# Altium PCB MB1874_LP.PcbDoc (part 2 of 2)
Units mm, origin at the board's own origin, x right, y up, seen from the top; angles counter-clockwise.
Board outline 59.8 x 34.35 mm, 2 copper layers (Top Layer, Bottom Layer), stack 0.78 mm thick; 77 components, 63 nets, 242 pads, 939 vias.
Unrouted connection lines stored in the file: 1.
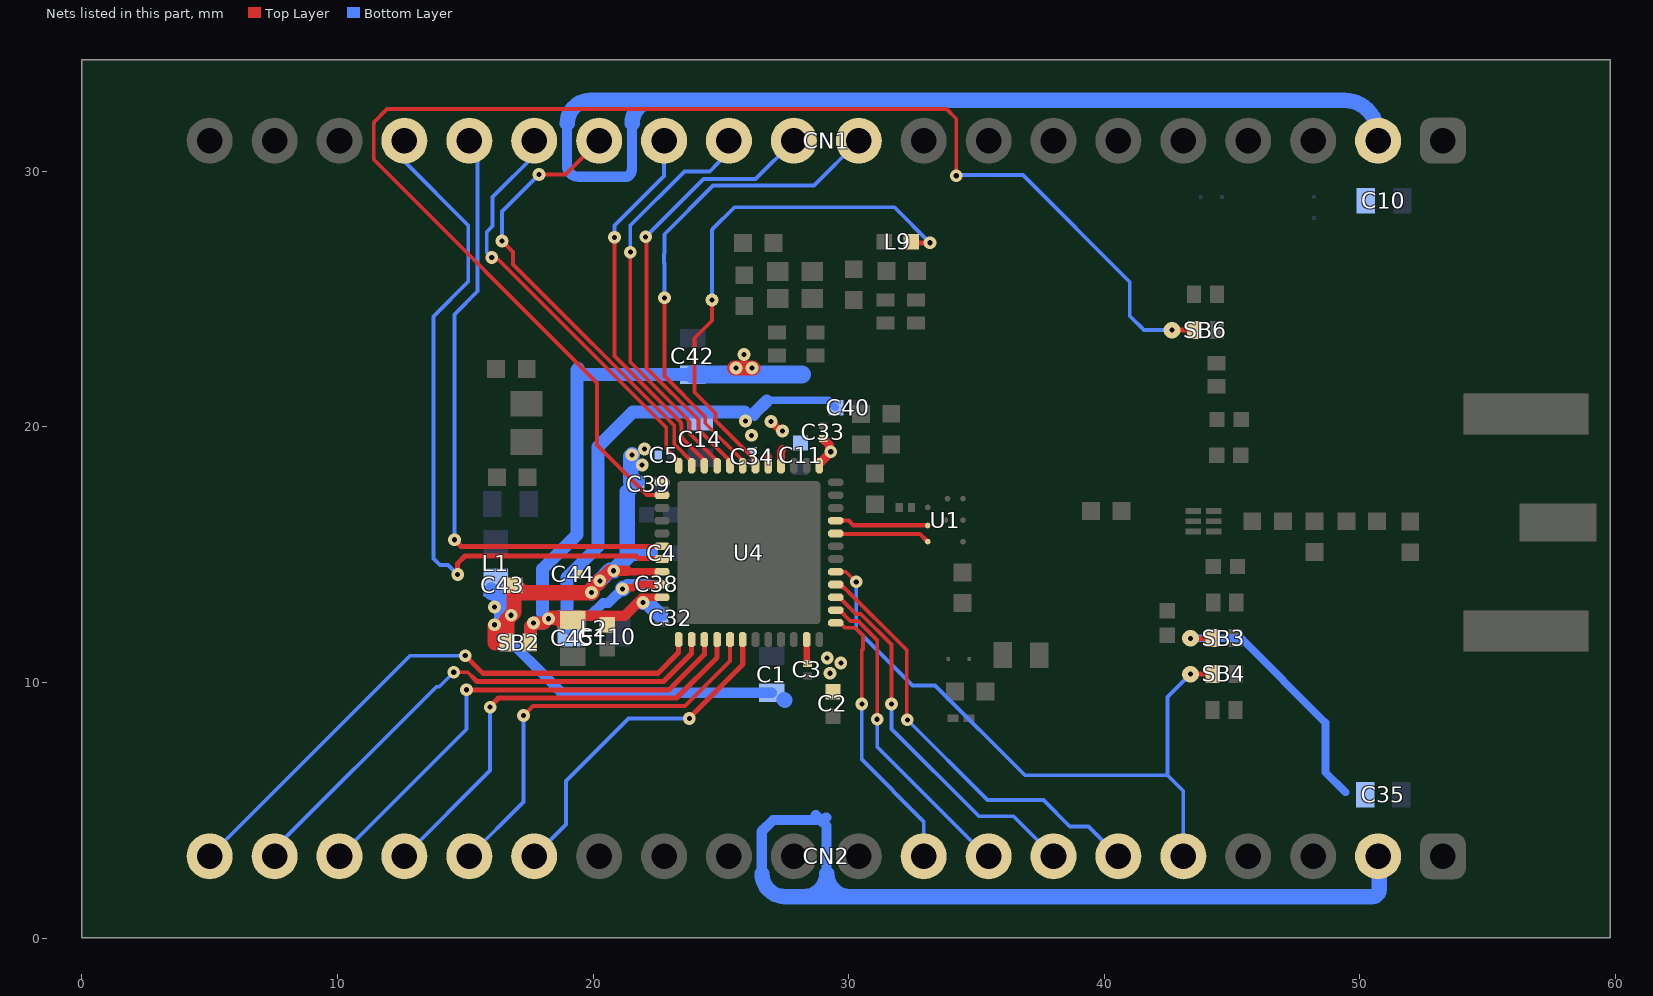
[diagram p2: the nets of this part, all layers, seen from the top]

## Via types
v1: diameter 0.5, hole 0.2, Top Layer to Bottom Layer, 933 vias
v2: diameter 0.65, hole 0.2, Top Layer to Bottom Layer, 6 vias

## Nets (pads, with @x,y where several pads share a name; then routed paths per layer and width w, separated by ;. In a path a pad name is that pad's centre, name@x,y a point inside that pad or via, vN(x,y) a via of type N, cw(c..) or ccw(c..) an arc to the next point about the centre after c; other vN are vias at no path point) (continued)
PA5: CN2.9 U4.13 | length 10.9
  Top Layer w0.15: U4.13@29.496,12.332 29.677,12.332 29.866,12.143 30.254,12.143 30.561,11.835 30.561,11.31 30.519,11.268 v1(30.519,9.16)
  Bottom Layer w0.15: v1(30.519,9.16) 30.519,6.983 32.94,4.563 CN2.9@32.94,3.2
PA6: CN2.8 U4.14 | length 12.4
  Top Layer w0.15: U4.14@29.496,12.832 29.646,12.832 30.065,12.413 30.366,12.413 31.12,11.659 v1(31.12,8.56)
  Bottom Layer w0.15: v1(31.12,8.56) 31.12,7.485 35.404,3.2 CN2.8@35.48,3.2
PA7: CN2.7 U4.15 | length 14.7
  Top Layer w0.15: U4.15@29.496,13.332 29.646,13.332 30.295,12.683 30.478,12.683 31.679,11.481 v1(31.679,9.16)
  Bottom Layer w0.15: v1(31.679,9.16) 31.679,8.184 35.098,4.765 36.455,4.765 CN2.7@38.02,3.2
PA8: CN2.6 U4.16 | length 17.1
  Top Layer w0.15: U4.16@29.496,13.832 29.713,13.832 29.785,13.76 29.785,13.722 29.823,13.722 32.28,11.265 v1@32.28,8.64
  Top Layer w0.2: v1@32.28,8.64 32.28,8.56 v1(32.299,8.54) 32.299,8.58 v1@32.32,8.6
  Bottom Layer w0.15: v1(32.299,8.54) 35.44,5.399 37.623,5.399 38.658,4.365 39.395,4.365 CN2.6@40.56,3.2
PA9: CN2.5 SB4.1 U4.17 | length 26
  Top Layer w0.15: U4.17@29.496,14.332 29.888,14.332 30.279,13.94 v1@30.279,13.88
  Top Layer w0.2: v2(43.381,10.328) 44.229,10.328 SB4.1@44.238,10.337
  Bottom Layer w0.15: v1(30.299,13.94) 30.299,12.097 30.561,11.835 30.561,11.825 32.501,9.885 33.386,9.885 36.902,6.37 42.482,6.37 ; CN2.5@43.1,3.2 43.1,5.752 42.482,6.37 ; v2(43.381,10.328) 42.482,9.429 42.482,6.37
PA10: CN1.12 U4.33 | length 16.3
  Top Layer w0.15: v1(21.46,26.84) 21.46,22.536 23.717,20.279 23.717,20.276 23.787,20.205 23.787,19.742 24.858,18.672 U4.33@24.858,18.482
  Bottom Layer w0.15: v1(21.46,26.84) 21.46,27.879 23.58,30 24.566,30 24.897,30.331 25.32,30.754 CN1.12@25.32,31.2
PA11: CN1.13 U4.34 | length 15
  Top Layer w0.15: v1(20.84,27.42) 20.84,22.774 23.447,20.167 23.447,20.115 23.466,20.096 23.466,19.584 U4.34@24.358,18.692
  Top Layer w0.2: U4.34@24.358,18.482 U4.34@24.358,18.692
  Bottom Layer w0.15: v1(20.84,27.42) 20.84,27.881 22.78,29.821 CN1.13@22.78,31.2
PA12: CN1.14 U4.35 | length 18.1
  Top Layer w0.15: v1@16.41,27.33 v1@16.49,27.33 ; v1(16.44,27.28) 16.87,26.85 16.87,26.362 23.177,20.055 23.177,19.332 23.858,18.651 U4.35@23.858,18.482 ; v1(17.89,29.883) 18.923,29.883 CN1.14@20.24,31.2
  Bottom Layer w0.15: v1(16.44,27.28) 16.44,28.429 17.61,29.6 17.61,29.604 v1(17.89,29.883)
PA13: CN1.15 U4.36 | length 16.7
  Top Layer w0.15: v1(16.039,26.626) 16.12,26.545 16.303,26.545 22.864,19.983 22.864,19.156 23.358,18.662 U4.36@23.358,18.482
  Bottom Layer w0.15: v1(16.039,26.626) 15.844,26.821 15.844,27.632 16.071,27.859 16.071,29 17.7,30.629 CN1.15@17.7,31.2
PA14: CN1.16 U4.42 | length 24.5
  Top Layer w0.2: v1(14.577,15.588) 14.845,15.32 22.757,15.32 U4.42@22.8,15.362
  Bottom Layer w0.15: v1(14.577,15.588) 14.577,24.404 15.481,25.308 15.481,30.879 CN1.16@15.16,31.2 CN1.16@15.147,31.188
PA15: CN1.17 U4.43 | length 27.8
  Top Layer w0.2: v1(14.704,14.228) 14.704,14.662 14.991,14.95 21.682,14.95 21.786,14.846 22.768,14.846 U4.43@22.792,14.87
  Bottom Layer w0.15: CN1.17@12.62,31.2 12.62,30.382 15.121,27.88 15.121,25.688 13.76,24.327 13.76,14.858 14.017,14.601 14.33,14.601 v1(14.704,14.228)
PB0: L9.2 U4.30 | length 20.9
  Top Layer w0.15: v1(24.654,24.973) 24.654,24.155 23.972,23.474 23.972,21.357 24.79,20.539 24.79,20.256 U4.30@26.358,18.688 ; U4.30@26.294,18.545 U4.30@26.358,18.482 U4.30@26.358,18.688 ; U4.30@26.358,18.694 U4.30@26.358,18.688
  Top Layer w0.2: L9.2@32.36,27.2 v1@33.191,27.2
  Bottom Layer w0.15: v1(24.654,24.973) 24.654,27.656 cw(c24.804,27.656) 24.698,27.763 25.535,28.6 31.791,28.6 v1@33.191,27.2
  other v1: 33.191,27.209
PB2: CN1.10 U4.31 | length 19.5
  Top Layer w0.15: v1(22.794,25.053) 22.794,21.992 24.394,20.392 24.394,20.147 25.858,18.684 U4.31@25.858,18.482
  Bottom Layer w0.15: v1(22.794,25.053) 22.794,26.405 22.775,26.424 22.775,26.776 22.794,26.795 22.794,27.542 24.702,29.45 28.65,29.45 CN1.10@30.4,31.2
PB3: CN2.20 U4.1 | length 22.7
  Top Layer w0.2: v1(15,11.05) 15.69,10.36 22.54,10.36 23.351,11.171 U4.1@23.351,11.685
  Bottom Layer w0.15: CN2.20@5,3.2 12.85,11.05 v1(15,11.05)
PB4: CN2.19 U4.2 | length 20.3
  Top Layer w0.15: v1(14.55,10.4) 15.1,10.4 15.278,10.222
  Top Layer w0.2: 15.278,10.222 15.463,10.037 22.757,10.037 23.858,11.138 U4.2@23.858,11.685
  Bottom Layer w0.15: CN2.19@7.54,3.502 13.87,9.832 13.982,9.832 v1(14.55,10.4)
PB5: CN2.18 U4.3 | length 19
  Top Layer w0.2: v1(15.048,9.715) 15.697,9.713 ; 15.698,9.713 22.973,9.713 24.358,11.098 U4.3@24.358,11.685
  Bottom Layer w0.15: CN2.18@10.08,3.2 15.048,8.168 v1(15.048,9.715)
PB6: CN2.17 U4.4 | length 17.6
  Top Layer w0.2: v1(15.975,9.035) 15.98,9.069 16.299,9.389 23.268,9.389 24.858,10.978 U4.4@24.858,11.685
  Bottom Layer w0.15: CN2.17@12.62,3.2 15.975,6.556 v1(15.975,9.035)
PB7: CN2.16 U4.5 | length 16.2
  Top Layer w0.15: v1@17.281,8.712 17.645,9.076 23.596,9.076 25.358,10.838 U4.5@25.358,11.685
  Bottom Layer w0.15: CN2.16@15.16,3.2 17.279,5.319 v1(17.279,8.71)
PB8: CN2.15 U4.6 | length 14.5
  Top Layer w0.15: U4.6@25.818,11.645 U4.6@25.858,11.685 U4.6@25.858,11.435
  Top Layer w0.2: v1@23.76,8.54 v1@23.8,8.58 ; v1@23.84,8.58 v1@23.8,8.58 ; U4.6@25.86,11.435 U4.6@25.86,11.76 ; U4.6@25.86,11.645 U4.6@25.86,11.76 ; v1@23.8,8.58 23.78,8.58 v1(23.77,8.59) 23.76,8.6 25.86,10.7 U4.6@25.86,11.76
  Bottom Layer w0.15: CN2.15@17.7,3.2 17.735,3.236 18.937,4.438 18.937,6.143 ; 19.115,6.321 18.937,6.143 ; v1(23.77,8.59) 21.384,8.59 18.937,6.143
PB12: CN1.11 U4.32 | length 17.6
  Top Layer w0.15: v1@22.1,27.38 22.1,22.305 24.124,20.28 24.124,19.896 25.358,18.663 U4.32@25.358,18.482
  Bottom Layer w0.15: v1(22.06,27.44) 24.32,29.7 26.36,29.7 CN1.11@27.86,31.2
PC13: SB6.1 U4.38 | length 57.6
  Top Layer w0.15: U4.38@22.698,17.332 22.11,17.332 20.154,19.288 20.154,21.725 11.42,30.46 11.42,31.92 11.939,32.44 33.832,32.44 34.213,32.058 v1(34.213,29.829)
  Top Layer w0.2: v2(42.658,23.789) SB6.1@43.506,23.789
  Bottom Layer w0.15: 11.42,31.92 11.427,31.913 ; v1(34.213,29.829) 34.244,29.859 36.82,29.859 41.005,25.675 41.005,24.342 41.558,23.789 v2(42.658,23.789)
RFI_N: U1.3 U4.21 | length 3.7
  Top Layer w0.164: U4.21@29.496,16.332 29.673,16.332 U4.21@29.684,16.32 ; U4.21@29.673,16.337 30.007,16.337 30.193,16.151 U1.3@33.081,16.151
RFI_P: U1.2 U4.20 | length 3.7
  Top Layer w0.164: U4.20@29.496,15.832 29.673,15.832 U4.20@29.682,15.823 ; U4.20@29.682,15.816 32.789,15.816 U1.2@33.079,15.526
VDD: C1.2 C2.2 C3.2 C4.2 C5.2 C35.2 C39.1 C43.2 C44.2 CN2.2 L1.1 SB2.2 SB3.1 U4.11 U4.37 U4.44 | length 77.6
  Top Layer w0.2: v2(43.381,11.728) 44.229,11.728 SB3.1@44.238,11.737
  Top Layer w0.254: U4.11@28.36,11.643 28.36,10.771 C3.2@28.391,10.739
  Top Layer w0.3: v1@20.77,14.287 v1@20.814,14.332 ; 21.214,14.392 21.345,14.392 21.405,14.332 U4.44@22.698,14.332
  Top Layer w0.4: v1(20.809,14.375) 21.327,14.375
  Top Layer w0.5: v1(20.267,13.98) 20.662,14.375 v1(20.809,14.375)
  Top Layer w0.6: v1@16.165,12.207 16.165,11.561 SB2.2@16.515,11.561 ; SB2.2@16.625,11.561 16.625,12.458 v1(16.797,12.63) 16.911,12.743 16.911,13.381 16.911,13.779 C43.2@16.943,13.811 17.235,13.518 v1(19.945,13.518) 19.945,13.658 v1(20.267,13.98)
  Bottom Layer w0.3: v2(43.381,11.728) 45.365,11.728 48.66,8.434 48.66,6.49 49.447,5.704
  Bottom Layer w0.4: v1@16.165,12.207 18.774,9.598 C1.2@26.998,9.598 ; 26.601,2.727 26.601,4.041 26.601,4.173 27.043,4.615 28.91,4.615 ; 28.719,4.806 28.91,4.615 ; 29.13,4.72 29.025,4.615 28.91,4.615 ; 29.141,2.727 29.141,4.041 29.141,4.384 28.91,4.615
  Bottom Layer w0.6: L1.1@16.011,13.537 16.011,13.613 16.42,13.203 16.42,12.479 ; v1(19.945,13.518) 19.945,13.658 v1(20.267,13.98) 20.267,13.999 v1@20.662,14.395 ; v1(20.809,14.375) 21.341,14.906 ; C39.1@21.478,17.857 21.478,18.857 v1(21.53,18.909) ; C39.1@21.724,17.857 21.341,17.474 21.341,15.319 ; C4.2@22.216,15.059 21.601,15.059 ; 26.611,2.526 ccw(c27.516,2.526) 27.516,1.621 50.487,1.621 ccw(c50.487,1.898) 50.764,1.898 50.764,3.155 ccw(c50.72,3.155) CN2.2@50.72,3.2 ; C1.2@27.485,9.33 27.51,9.305 ; 28.245,1.621 ccw(c28.245,2.526) 29.151,2.526 ccw(c30.056,2.526) 30.056,1.621 ; 21.341,14.906 21.494,15.059 21.601,15.059 ; 21.341,14.906 21.341,15.319 ; 21.341,15.319 21.601,15.059
  other v1: 29.274,10.364 29.698,10.763 29.162,10.959 16.141,12.259 16.141,12.959 21.924,18.515 22.015,19.137
VDDPA: C14.1 C33.2 C34.2 C38.1 C40.1 L2.1 U4.25 U4.29 U4.45 | length 25
  Top Layer w0.3: v1(21.159,13.666) 21.197,13.704 21.559,13.704 21.687,13.832 U4.45@22.698,13.832 ; U4.29@26.858,18.482 26.858,18.835
  Top Layer w0.35: U4.25@28.887,18.632 28.923,18.632 29.354,19.063 29.26,19.063 29.26,19.279 C33.2@29.062,19.477
  Bottom Layer w0.3: L2.1@18.981,12.386 19.089,12.279 L2.1@19.247,12.12 ; v1@21.108,13.666 v1(21.159,13.666) v1@21.213,13.666 ; 26.321,20.39 26.321,20.54 ; 26.798,21.017 26.798,21.047 ; 26.798,21.092 26.798,21.047 ; C40.1@29.469,20.778 29.2,21.047 26.798,21.047
  Bottom Layer w0.4: L2.1@19.089,12.279 19.089,12.329 19.369,12.609 19.889,12.609 20.389,13.109 20.602,13.109 v1(21.159,13.666) ; v1@21.178,13.685 21.338,13.845 C38.1@22.138,13.845
  Bottom Layer w0.5: L2.1@19.089,12.109 18.981,12.217 18.981,12.386 18.981,14.107 20.196,15.322 20.196,19.228 21.555,20.587 25.927,20.587 ; 26.321,20.54 26.798,21.017
  Bottom Layer w0.6: v1(21.159,13.666) v1@21.178,13.685
  other v1: 29.304,19.029 26.206,19.672 25.972,20.237
VDDRF: C10.1 C11.1 C32.2 C42.1 C45.1 C110.1 CN1.2 SB2.1 U4.28 U4.46 | length 77.8
  Top Layer w0.3: v1@21.836,13.182 v1@21.89,13.182 ; v1@21.898,13.332 U4.46@22.698,13.332 U4.46@22.708,13.332 ; v1(26.964,20.214) 27.334,19.845 v1(27.419,19.845) ; U4.28@27.358,18.482 27.358,19.041 27.401,19.085 27.401,19.139
  Top Layer w0.4: v1(18.254,12.496) 18.37,12.612 21.24,12.612 ; 18.621,12.612 21.24,12.612 ; C45.1@18.734,12.612 21.24,12.612 ; C45.1@19.211,12.612 21.24,12.612 ; v1@21.836,13.182 v1@21.809,13.182 ; v1@21.876,13.249 v1@21.809,13.182 ; 21.24,12.612 v1@21.809,13.182
  Top Layer w0.5: SB2.1@17.525,11.561 17.55,11.586 17.55,12.201 v1(17.674,12.324) 18.082,12.324 v1(18.254,12.496) 18.621,12.496 C45.1@18.734,12.383
  Top Layer w0.6: v1@25.549,22.308 v1@26.249,22.308
  Bottom Layer w0.2: 22.591,12.659 22.652,12.598 22.753,12.598 22.793,12.558 C32.2@22.793,12.523
  Bottom Layer w0.4: 18.981,31.673 18.981,30.359 18.981,30.219 ccw(c19.386,30.219) 19.099,29.932 ccw(c19.445,30.278) 19.445,29.789 21.304,29.789 ccw(c21.304,29.938) 21.409,29.833 ccw(c21.14,30.102) 21.521,30.102 21.521,30.359 21.521,31.673
  Bottom Layer w0.5: v1(17.674,12.324) 18.082,12.324 v1(18.254,12.496) 18.028,12.721 18.028,14.441 19.37,15.783 19.37,22.241 ; 19.423,22.294 19.37,22.241 ; C42.1@23.904,22.048 19.562,22.048 19.37,22.241
  Bottom Layer w0.6: 18.991,31.874 cw(c19.896,31.874) 19.896,32.779 22.436,32.779 ; 21.531,31.874 cw(c22.436,31.874) 22.436,32.779 ; v1(21.958,13.13) 22.12,13.13 22.591,12.659 ; CN1.2@50.72,31.2 50.72,31.422 ccw(c49.331,31.422) 50.313,32.404 ccw(c49.407,31.498) 49.407,32.779 22.436,32.779
  Bottom Layer w0.7: C42.1@23.893,22.059 28.183,22.059
  other v1: 25.592,22.302 26.217,22.302 25.904,22.839
pads on no net: U4.23
copper on no net: | length 927.9
  Top Layer w0.381: 101.042,10.009 111.454,10.009 135.07,10.009 156.908,10.009 173.413,10.009 187.888,10.009 ; 101.042,13.057 111.454,13.057 135.07,13.057 156.908,13.057 173.413,13.057 187.888,13.057 ; 101.042,16.105 111.454,16.105 135.07,16.105 156.908,16.105 173.413,16.105 187.888,16.105 ; 101.042,19.153 111.454,19.153 135.07,19.153 156.908,19.153 173.413,19.153 187.888,19.153 ; 101.042,22.201 111.454,22.201 135.07,22.201 156.908,22.201 173.413,22.201 187.888,22.201 ; 101.042,25.249 111.454,25.249 135.07,25.249 156.908,25.249 173.413,25.249 187.888,25.249 ; 101.042,28.297 187.888,28.297 ; 111.454,31.345 111.454,6.961 ; 135.07,31.345 135.07,6.961 ; 156.908,31.345 156.908,6.961 ; 173.413,31.345 173.413,6.961 ; 111.454,6.961 101.042,6.961 101.042,31.345 187.888,31.345 187.888,6.961 173.413,6.961 ; 111.454,6.961 135.07,6.961 ; 135.07,6.961 156.908,6.961 ; 156.908,6.961 173.413,6.961

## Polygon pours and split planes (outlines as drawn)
GND on Top Layer "GND_L01_P004" (solid, remove dead copper, pour order 4): 0.007,34.428 59.685,34.428 59.8,34.313 59.8,0.087 -0.166,0.087 -0.166,34.313 -0.108,34.37
GND on Bottom Layer "GND_L02_P002" (solid, remove dead copper, pour order 2): 0,34.363 59.8,34.363 59.8,0.009 0,0.009

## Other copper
Top Layer:
  region net VDDRF: 26.805,20.012 26.756,20.061 cw(c26.912,20.217) 26.691,20.217 26.691,20.287 ccw(c26.254,20.288) 26.563,20.597 25.441,21.718 cw(c25.914,22.191) 25.246,22.191 25.246,22.596 cw(c25.797,22.596) 25.797,23.148 26.059,23.148 cw(c26.059,22.594) 26.613,22.594 26.613,22.01 ccw(c27.464,22.01) 26.862,21.408 27.274,20.996 cw(c26.924,20.645) 27.419,20.645 27.419,19.845
  region net VDD: 22.66,17.683 22.507,17.683 cw(c22.507,18.202) 22.14,17.835 21.296,18.679 cw(c21.533,18.917) 21.296,19.154 21.621,19.479 cw(c21.978,19.122) 22.336,19.479 cw(c22.052,19.195) 22.454,19.195 22.454,18.511 ccw(c23.158,18.511) 22.626,18.05 cw(c22.519,17.957) 22.66,17.957
  region net VDD: 16.641,11.896 16.076,11.896 cw(c16.076,12.15) 15.822,12.15 15.822,12.967 cw(c16.141,12.967) 16.141,13.286 16.836,13.286 cw(c16.836,12.975) 17.146,12.975 17.146,12.578 cw(c16.719,12.578) 17.021,12.276
  region net VDDRF: 22.071,12.916 ccw(c22.066,12.327) 21.653,12.747 21.514,12.886 21.809,13.182
  region net VDDRF: 17.489,12.488 17.76,12.76 cw(c17.886,12.634) 17.886,12.812 21.13,12.812 21.844,12.895 20.943,12.087 17.617,12.06 cw(c17.617,12.119) 17.567,12.087 17.489,12.204
  region net VDD: 28.291,10.835 28.291,11.123 28.629,11.123 28.791,11.182 cw(c29.263,9.896) 29.263,11.266 29.422,11.266 cw(c29.422,10.906) 29.56,11.238 cw(c29.154,10.258) 29.905,11.008 29.956,10.957 cw(c29.725,10.726) 30.052,10.726 30.052,10.047 cw(c29.35,10.047) 29.846,9.55 29.603,9.307 29.003,9.307 28.999,10.464 ccw(c28.696,10.464) 28.814,10.742 28.596,10.835
  region net VDD: 20.609,14.029 20.714,14.029 ccw(c20.714,14.595) 21.115,14.194 20.809,14.375
  region net NetC25_1: 44.175,16.421 44.616,16.421 ccw(c44.616,17.187) 44.906,16.478 45.348,16.659 45.611,16.659 45.611,15.959 45.33,15.959 44.854,16.16 ccw(c44.672,15.729) 44.672,16.197 44.175,16.197
  region net VDDRF: 27.202,18.78 27.202,19.215 ccw(c26.234,19.215) 26.919,19.9 26.751,20.068 cw(c26.872,20.188) 26.702,20.188 26.702,20.269 cw(c26.84,20.269) 26.742,20.366 26.817,20.442 cw(c26.899,20.36) 26.899,20.475 27.034,20.475 cw(c27.034,20.161) 27.256,20.383 27.589,20.05 cw(c27.361,19.821) 27.684,19.826 cw(c27.461,19.851) 27.661,19.75 27.661,19.06 cw(c27.543,19.06) 27.626,18.976 27.517,18.78
  region net VDDPA: 24.917,21.087 ccw(c25.144,20.939) 24.952,20.747 25.036,20.664 25.109,20.374 ccw(c25.444,20.459) 25.206,20.208 26.768,18.728 27.004,18.728 27.004,18.857 ccw(c26.435,18.857) 26.837,19.26 26.702,19.395 cw(c26.932,19.625) 26.607,19.625 26.607,19.657 26.607,19.741 ccw(c25.507,19.742) 26.284,20.52 25.751,21.053 ccw(c25.306,20.609) 25.306,21.238 25.196,21.238 ccw(c25.196,20.905)
  region net NetC19_1: 43.568,16.821 43.128,16.821 cw(c43.128,17.587) 42.838,16.878 42.396,17.059 42.133,17.059 42.133,16.359 42.414,16.359 42.89,16.56 cw(c43.072,16.129) 43.072,16.597 43.568,16.597
  region net NetC27_2: 43.205,15.965 cw(c42.499,16.26) 42.912,15.616 42.511,15.357 42.36,15.142 42.877,14.78 ccw(c42.917,14.836) 42.972,14.797 43.094,14.971 43.203,15.476 cw(c43.661,15.377) 43.277,15.646 43.403,15.826
  region net VDDPA: 28.835,19.432 28.835,18.735 29.144,18.735 29.364,18.955 29.357,18.963 29.357,19.391 29.166,19.581 28.835,19.581 28.835,19.466 28.831,19.462
  pour cut-out: 16.74,20.38 18.04,20.38 18.04,19.88 16.74,19.88
  pour cut-out: 27.26,18.7 27.26,20.9 24.94,23.22 24.94,26 26.1,26 26.1,27.809 33.241,27.809 33.591,27.459 33.591,23.91 32.5,22.6 30.36,22.6 28.82,21.06 28.82,19.02 28.5,18.7
  pour cut-out: 20.78,13.26 21.34,13.26 21.36,13.24 21.36,12.92 20.78,12.92 20.76,12.94 20.76,13.24
  pour cut-out: 28.12,10.74 28.68,10.74 28.7,10.72 28.7,10.4 28.12,10.4 28.1,10.42 28.1,10.72
  region net VDD: 19.359,14.406 19.509,14.556 20.691,14.556 20.962,14.285 19.993,13.316 19.359,13.316
  pour cut-out: 22.919,18.24 29.24,18.24 29.18,18.18 29.18,11.96 23.52,11.96 23.52,12.54 22.919,12.54
  pour cut-out: 31.75,27.6 32.15,27.6 32.15,26.8 31.75,26.8
  pour cut-out: 34.604,10.544 35.1,10.544 35.1,9 34.492,9
  region net GND: 28.9,25.4 30.9,25.4 31.141,25.159 31.141,24.6 30.3,24.6 29.2,24.6 29.1,24.7 28.9,24.7
  pour cut-out: 26.3,27.6 26.8,27.6 26.8,26.7 26.7,26.8 26.3,26.8
  pour cut-out: 31.855,26.51 32.355,26.51 32.355,25.81 32.255,25.71 31.855,25.71
  region net NetC28_1: 54.913,16.605 56.112,17.012 56.347,17.012 56.347,15.525 56.214,15.525 54.913,15.98
  pour cut-out: 29.796,17.875 31.613,17.875 31.613,17.306 29.796,17.306
  pour cut-out: 30.556,17.307 33.499,17.307 33.499,15.02 30.556,15.02
  pour cut-out: 56.088,18.027 56.077,18.016 56.077,14.642 59.179,14.642 59.19,14.653 59.19,18.033 56.088,18.033 56.083,18.027
  pour cut-out: 55.034,16.911 56.108,17.985 56.108,16.939 56.08,16.911
  pour cut-out: 54.952,15.696 54.952,15.68 56.053,14.579 56.097,14.622 56.097,15.68 54.985,15.68 54.974,15.691
  text "Layer" at 102.82,29.059 h1.52
  text "Name" at 113.232,29.059 h1.52
  text "Material" at 136.848,29.059 h1.52
  text "Thickness" at 158.686,29.059 h1.52
  text "Constant" at 175.191,29.059 h1.52
  text "Top Overlay" at 113.232,26.011 h1.52
  text "Top Solder" at 113.232,22.963 h1.52
  text "Solder Resist" at 136.848,22.963 h1.52
  text "1.18mil" at 158.686,22.963 h1.52
  text "3.5" at 175.191,22.963 h1.52
  text "1" at 102.82,19.915 h1.52
  text "Top Layer" at 113.232,19.915 h1.52
  text "1.38mil" at 158.686,19.915 h1.52
  text "Dielectric 1" at 113.232,16.867 h1.52
  text "FR-4" at 136.848,16.867 h1.52
  text "27.95mil" at 158.686,16.867 h1.52
  text "5" at 175.191,16.867 h1.52
  text "2" at 102.82,13.819 h1.52
  text "Bottom Layer" at 113.232,13.819 h1.52
  text "1.38mil" at 158.686,13.819 h1.52
  text "Bottom Solder" at 113.232,10.771 h1.52
  text "Solder Resist" at 136.848,10.771 h1.52
  text "1.18mil" at 158.686,10.771 h1.52
  text "3.5" at 175.191,10.771 h1.52
  text "Bottom Overlay" at 113.232,7.723 h1.52
  text ".Layer_Name" at 9.421,-20.18 h3
  text ".GTL" at 51.116,-20.18 h3
Bottom Layer:
  region net VDDRF: 25.137,21.913 25.14,22.454 cw(c25.669,22.45) 25.295,22.824 25.5,23.029 cw(c25.768,22.761) 25.768,23.14 26.032,23.14 cw(c26.032,22.762) 26.299,23.029 26.398,22.93 cw(c25.774,22.306) 26.656,22.306 26.656,21.913
  region net VDD: 50.494,4.444 50.582,5.898 50.376,6.103 49.318,6.103 49.121,5.906 49.121,4.245 49.502,3.864 49.481,1.73 50.439,1.73 ccw(c50.552,3.086)
  region net VDDRF: 26.813,20.479 27.058,20.479 cw(c27.058,20.307) 27.206,20.396 27.316,20.212 ccw(c27.475,20.308) 27.475,20.122 27.967,20.122 cw(c27.967,19.851) 28.159,20.043 28.315,19.887 cw(c28.054,19.626) 28.423,19.625 28.423,19.069 27.633,19.065 26.726,20.09 cw(c26.859,20.158) 26.71,20.158 26.71,20.376 cw(c26.813,20.376)
  region net VDDPA: 23.666,19.863 23.666,20.413 24.462,21.209 cw(c24.979,20.691) 24.979,21.423 26.238,21.423 26.238,20.517 ccw(c26.326,20.517) 26.327,20.429 cw(c26.327,20.273) 26.483,20.273 26.483,19.121 cw(c26.4,19.121) 26.4,19.039 26.052,19.039 cw(c26.052,19.337) 25.754,19.337 25.754,19.785 ccw(c25.676,19.785) 25.676,19.863
  region net VDD: 22.029,17.566 22.029,18.177 cw(c22.211,18.177) 22.082,18.305 22.488,18.711 22.688,18.711 22.697,18.721 22.697,19.069 22.681,19.086 22.582,19.086 22.283,19.384 ccw(c22.098,19.199) 22.098,19.461 21.39,19.461 ccw(c21.39,19.289) 21.219,19.289 21.219,17.759 ccw(c21.429,17.759) 21.431,17.548 22.016,17.553 ccw(c22.016,17.566)
  region net VDDRF: 50.494,29.956 50.582,28.502 50.376,28.297 49.318,28.297 49.121,28.494 49.121,30.155 49.502,30.536 49.481,32.67 50.439,32.67 cw(c50.552,31.314)
  region net VDDRF: 19.116,30.072 21.714,30.072 21.714,29.746 cw(c21.535,29.746) 21.535,29.568 19.7,29.568 19.7,22.756 ccw(c20.158,22.756) 20.158,22.298 20.339,22.298 19.116,22.027
  region net VDD: 29.048,11.274 29.656,11.274 cw(c29.656,11.08) 29.793,11.217 29.933,11.077 cw(c29.764,10.908) 30.004,10.907 30.004,10.431 cw(c29.655,10.431) 29.655,10.082 29.066,10.082 cw(c29.066,10.327) 28.821,10.327 28.821,11.047 cw(c29.048,11.047)
  region net VDD: 26.501,4.377 26.782,4.658 cw(c27.606,3.835) 27.606,4.999 28.745,4.999 28.745,7.983 26.49,9.342 26.493,9.967 27.48,9.967 28.118,9.017 ccw(c28.479,9.259) 28.479,8.824 28.529,8.824 ccw(c28.529,9.25) 28.955,9.25 28.955,10.959 29.589,10.959 29.589,4.642 cw(c29.243,4.642) 29.243,4.297 26.533,4.301 cw(c26.533,4.345)
  region net VDD: 16.641,11.896 16.076,11.896 cw(c16.076,12.15) 15.822,12.15 15.822,13.286 16.836,13.286 cw(c16.836,12.975) 17.146,12.975 17.146,12.578 cw(c16.719,12.578) 17.021,12.276
  region net VDDRF: 17.623,12.101 17.414,12.31 17.414,12.459 cw(c17.796,12.459) 17.526,12.73 17.671,12.875 cw(c17.8,12.746) 17.801,12.928 18.332,12.928 cw(c18.332,12.785) 18.475,12.785 18.475,12.308 cw(c18.303,12.308) 18.424,12.186 18.399,12.161 cw(c18.262,12.298) 18.263,12.104
  region net VDDPA: 28.339,20.513 28.766,20.086 28.766,18.917 28.963,18.72 29.667,18.72 29.864,18.917 29.864,19.039 29.864,20.544 29.844,20.523 28.349,20.523
  region net VDDPA: 26.208,21.418 26.221,21.405 29.619,21.405 29.87,21.155 29.87,20.477 27.726,20.477 27.437,20.766 26.095,20.766 26.095,21.292 26.221,21.418
  pour cut-out: 16.7,15.42 18.42,15.42 18.42,14.7 18.46,14.66 18.44,14.64 18.44,13.74 16.78,13.74 16.7,13.82
  pour cut-out: 19.78,12.72 20.58,12.72 20.58,11.32 19.78,11.32
  region net GND: 28.1,28.25 30.3,28.25 30.3,24.2 29.6,24.2 29.6,24.6 28.1,24.6
  pour cut-out: 27.26,18.691 27.26,20.891 24.94,23.211 24.94,25.991 26.1,25.991 26.1,27.8 33.241,27.8 33.591,27.45 33.591,23.9 32.5,22.591 30.36,22.591 28.82,21.051 28.82,19.011 28.5,18.691
  text ".GBL" at 39.743,-15.212 h3
  text ".Layer_Name" at 81.057,-15.212 h3

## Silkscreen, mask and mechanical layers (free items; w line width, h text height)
Top Overlay:
  region: 4.369,24.255 4.369,11.279 10.565,11.279 10.565,24.255
  lines w0.15: 2.042,31.305 2.042,31.805 ; 2.38,31.055 2.38,32.055 ; 2.717,30.901 2.717,32.208 ; 2.72,31.55 3.73,31.55 ; 39.911,32.963 41.218,32.963 ; 40.064,33.3 41.064,33.3 ; 40.314,33.638 40.814,33.638 ; 40.56,32.25 40.56,32.95 ; 44.991,32.963 46.298,32.963 ; 45.144,33.3 46.144,33.3 ; 45.394,33.638 45.894,33.638 ; 45.64,32.25 45.64,32.95 ; 47.531,32.963 48.838,32.963 ; 47.684,33.3 48.684,33.3 ; 47.934,33.638 48.434,33.638 ; 48.18,32.25 48.18,32.95 ; 52.611,32.963 53.918,32.963 ; 52.764,33.3 53.764,33.3 ; 53.014,33.638 53.514,33.638 ; 53.26,32.25 53.26,32.95 ; 54.014,4.149 54.889,4.654 ; 54.567,5.217 55.22,4.085 ; 54.936,5.253 55.436,4.387 ; 55.354,5.205 55.604,4.772
  text "VDDRF" at 49.245,32.744 h1
  text "PA15" at 11.542,32.726 h1
  text "PA14" at 14.231,32.726 h1
  text "PA13" at 16.913,32.726 h1
  text "PA12" at 19.597,32.726 h1
  text "PA11" at 22.275,32.726 h1
  text "PA10" at 24.836,32.726 h1
  text "PB12" at 27.518,32.726 h1
  text "PB2" at 30.195,32.726 h1
  text "VRPA" at 42.07,32.611 h1
  text "Notes:" at 4.932,25.09 h1.2
  text "MB1848-LP" at 1.941,23.958 h2.5 r270
  text "PB3" at 4.184,1.124 h1
  text "PB4" at 6.743,1.127 h1
  text "PB5" at 9.3,1.127 h1
  text "PB6" at 11.864,1.125 h1
  text "PB7" at 14.424,1.127 h1
  text "PB8" at 16.983,1.125 h1
  text "PA0" at 19.543,1.125 h1
  text "PA1" at 22.1,1.125 h1
  text "PA2" at 24.536,1.125 h1
  text "PA3" at 27.089,1.124 h1
  text "PA4" at 29.648,1.127 h1
  text "PA5" at 32.205,1.127 h1
  text "PA6" at 34.769,1.125 h1
  text "PA7" at 37.328,1.127 h1
  text "PA8" at 39.887,1.125 h1
  text "PA9" at 42.447,1.125 h1
  text "NRST" at 44.514,1.131 h1
  text "VDD" at 49.344,0.79 h1.5
  text ".Layer_Name" at 9.421,-20.18 h3
  text ".GTO" at 51.116,-20.18 h3
Bottom Overlay:
  region: 45.405,14.623 32.229,14.623 32.229,5.511 45.405,5.511
  text "Notes:" at 45.105,14.863 h1.2
  text "MB1874A-LP" at 15.644,6.693 h2.5
  text ".GBO" at 39.743,-15.212 h3
  text ".Layer_Name" at 81.057,-15.212 h3
Top Paste:
  lines w0.5: 13.14,26.72 cw(c14.99,26.72) 14.99,28.57 ; 13.149,9.153 13.149,26.653 ; 13.16,9.22 ccw(c15.01,9.22) 15.01,7.37 ; 14.98,7.34 51.88,7.34 ; 14.98,28.58 51.88,28.58 ; 51.89,28.59 cw(c51.89,26.74) 53.74,26.74 ; 51.93,7.35 ccw(c51.93,9.2) 53.78,9.2 53.78,15.24 ; 53.74,17.697 53.74,26.69
  text ".Layer_Name" at 9.421,-20.18 h3
  text ".GTP" at 51.116,-20.18 h3
Bottom Paste:
  text ".GBP" at 39.743,-15.212 h3
  text ".Layer_Name" at 81.057,-15.212 h3
Top Solder:
  lines w1.5: 53.724,17.818 53.724,26.506 ; 53.749,14.923 53.749,9.213 cw(c51.899,9.213) 51.899,7.363 14.999,7.363 cw(c14.999,9.213) 13.149,9.213 13.149,26.713 cw(c14.999,26.713) 14.999,28.563 51.899,28.563 cw(c51.899,26.713) 53.749,26.713
  text ".Layer_Name" at 9.421,-20.18 h3
  text ".GTS" at 51.116,-20.18 h3
Bottom Solder:
  text ".GBS" at 39.743,-15.212 h3
  text ".Layer_Name" at 81.057,-15.212 h3
Board:
  lines w0.3: 0,0 0,34.4 59.8,34.4 59.8,0 0,0
Dimensions:
  circle w0.2: c5,3.2 r0.9
  text ".Layer_Name" at 9.421,-20.18 h3
  text ".GM2" at 51.116,-20.18 h3
Top Assembly:
  lines w0.1: 0,0 59.8,0 59.8,34.4 0,34.4 0,0
  text "1" at 30.991,17.214 h0.5
  text "3" at 30.394,16.664 h0.5
  text "2" at 30.944,16.664 h0.5
  text ".Layer_Name" at 9.421,-20.18 h3
  text ".GM14" at 51.116,-20.18 h3
Bottom Assembly:
  circle w0.2: c74,17.2 r0.61
  circle w0.2: c74,17.2 r1.205
  circle w0.2: c-9,43 r1.205
  circle w0.2: c-9,43 r0.61
  circle w0.2: c-9,-9 r1.205
  circle w0.2: c-9,-9 r0.61
  lines w0.1: 0,0 0,34.4 59.8,34.4 59.8,0 0,0
  lines w0.2: -11.1,-9 -6.9,-9 ; -11.1,43 -6.9,43 ; -9,-11.09 -9,-6.9 ; -9,40.91 -9,45.1 ; 71.9,17.2 76.1,17.2 ; 74,15.11 74,19.3
  text ".GM15" at 39.743,-15.212 h3
  text ".Layer_Name" at 81.057,-15.212 h3
Drill Drawing:
  lines w0.2: 1.174,76.113 30.924,76.113 ; 0.174,44.113 144.924,44.113 144.924,79.613 138.674,79.613 0.174,79.613 0.174,50.363 0.174,44.113 ; 0.924,45.363 3.424,45.363 3.424,47.863 0.924,47.863 0.924,45.363 ; 0.924,54.363 0.924,56.863 3.424,56.863 3.424,54.363 0.924,54.363 ; 39.424,54.363 41.924,54.363 41.924,56.863 39.424,56.863 39.424,54.363 ; 39.424,57.363 41.924,57.363 41.924,59.863 39.424,59.863 39.424,57.363 ; 39.424,60.363 41.924,60.363 41.924,62.863 39.424,62.863 39.424,60.363 ; 39.424,63.363 41.924,63.363 41.924,65.863 39.424,65.863 39.424,63.363 ; 39.424,66.363 41.924,66.363 41.924,68.863 39.424,68.863 39.424,66.363 ; 55.924,54.363 55.924,56.863 58.424,56.863 58.424,54.363 55.924,54.363 ; 55.924,57.363 55.924,59.863 58.424,59.863 58.424,57.363 55.924,57.363 ; 55.924,60.363 55.924,62.863 58.424,62.863 58.424,60.363 55.924,60.363 ; 55.924,63.363 55.924,65.863 58.424,65.863 58.424,63.363 55.924,63.363 ; 55.924,66.363 55.924,68.863 58.424,68.863 58.424,66.363 55.924,66.363 ; 55.924,72.363 58.424,72.363 58.424,74.863 55.924,74.863 55.924,72.363 ; 64.924,48.363 64.924,50.863 67.424,50.863 67.424,48.363 64.924,48.363 ; 74.174,63.363 76.674,63.363 76.674,65.863 74.174,65.863 74.174,63.363 ; 74.174,66.363 76.674,66.363 76.674,68.863 74.174,68.863 74.174,66.363 ; 74.174,72.363 74.174,74.863 76.674,74.863 76.674,72.363 74.174,72.363 ; 90.174,48.363 92.674,48.363 92.674,50.863 90.174,50.863 90.174,48.363 ; 90.174,57.363 92.674,57.363 92.674,59.863 90.174,59.863 90.174,57.363 ; 90.174,60.363 92.674,60.363 92.674,62.863 90.174,62.863 90.174,60.363 ; 90.174,66.363 92.674,66.363 92.674,68.863 90.174,68.863 90.174,66.363 ; 90.174,72.363 90.174,74.863 92.674,74.863 92.674,72.363 90.174,72.363
  lines w0.254: 1.94,98.143 3.634,98.143 3.634,99.836 1.94,99.836 1.94,98.143 ; 1.94,103.646 3.634,103.646 2.787,101.953 1.94,103.646
  lines w0.381: 0.422,97 178.478,97 ; 0.422,104.62 178.478,104.62 ; 14.414,93.19 14.414,108.43 ; 29.65,93.19 29.65,108.43 ; 57.328,93.19 57.328,108.43 ; 70.177,93.19 70.177,108.43 ; 88.816,93.19 88.816,108.43 ; 126.904,93.19 126.904,108.43 ; 141.886,93.19 141.886,108.43 ; 160.83,93.19 160.83,108.43 ; 0.422,93.19 178.478,93.19 178.478,108.43 0.422,108.43 0.422,93.19
  text "Symbol" at 2.708,105.763 h1.83
  text "Count" at 15.557,105.763 h1.83
  text "Hole Size" at 30.793,105.763 h1.83
  text "Plated" at 58.471,105.763 h1.83
  text "Hole Type" at 71.32,105.763 h1.83
  text "Drill Layer Pair" at 89.959,105.763 h1.83
  text "Via/Pad" at 128.047,105.763 h1.83
  text "Pad Shape" at 143.029,105.763 h1.83
  text "Template" at 161.973,105.763 h1.83
  text "939" at 15.557,101.953 h1.52
  text "0.200mm (7.87mil)" at 30.793,101.953 h1.52
  text "PTH" at 58.471,101.953 h1.52
  text "Round" at 71.32,101.953 h1.52
  text "Top Layer - Bottom Layer" at 89.959,101.953 h1.52
  text "Via" at 128.047,101.953 h1.52
  text "Rounded" at 143.029,101.953 h1.52
  text "(Mixed)" at 161.973,101.953 h1.52
  text "40" at 15.557,98.143 h1.52
  text "1.000mm (39.37mil)" at 30.793,98.143 h1.52
  text "PTH" at 58.471,98.143 h1.52
  text "Round" at 71.32,98.143 h1.52
  text "Top Layer - Bottom Layer" at 89.959,98.143 h1.52
  text "Pad" at 128.047,98.143 h1.52
  text "(Mixed)" at 143.029,98.143 h1.52
  text "(Mixed)" at 161.973,98.143 h1.52
  text "979 Total" at 15.557,94.333 h1.52
  text "PCB SPECIFICATIONS :" at 1.174,76.613 h3
  text "A.   MATERIAL :" at 1.174,72.613 h3
  text "FR-4" at 39.674,72.613 h3
  text "X  TG-170" at 56.174,72.613 h3
  text "TG-150" at 74.424,72.613 h3
  text "TG-140" at 90.424,72.613 h3
  text "B.   MATERIAL FAMILY :" at 1.174,69.613 h3
  text "N/A" at 39.674,69.613 h3
  text "C.   SOLDERMASK COLOR :" at 1.174,66.613 h3
  text "X   GREEN" at 39.674,66.613 h3
  text "BLUE" at 56.174,66.613 h3
  text "RED" at 74.424,66.613 h3
  text "BLACK" at 90.424,66.613 h3
  text "D.   SILKSCREEN COLOR :" at 1.174,63.613 h3
  text "X  WHITE" at 39.674,63.613 h3
  text "YELLOW" at 56.174,63.613 h3
  text "BLACK" at 74.424,63.613 h3
  text "E.   SURFACE FINISH :" at 1.174,60.613 h3
  text "X  ENIG" at 39.674,60.613 h3
  text "IMMERSION SILVER" at 56.174,60.613 h3
  text "IMMERSION TIN" at 90.424,60.613 h3
  text "HASL" at 39.674,57.613 h3
  text "HASL (PB-FREE)" at 56.174,57.613 h3
  text "GOLDEN FINGER" at 90.424,57.613 h3
  text "F.   IMPEDANCE CONTROL :" at 1.174,54.613 h3
  text "NO" at 39.674,54.613 h3
  text "X  YES  (SEE IMPEDANCE TABLE FOR DETAIL INFORMATION)" at 56.174,54.613 h3
  text "G.   THROUGH VIA :" at 1.174,51.613 h3
  text "PLUG THE VIAS WHICH ARE COVERED WITH SOLDERMASK ONE OR TWO SIDE." at 39.674,51.613 h3
  text "PLUG MATERIAL :" at 39.674,48.613 h3
  text "X  SOLDERMASK" at 65.174,48.613 h3
  text "NON-CONDUCTIVE EPOXY." at 90.424,48.613 h3
  text "H.   STACK-UP :" at 1.174,45.613 h3
  text "SEE LAYER STACK-UP SEQUENCE FOR OVERALL THICKNESS." at 39.674,45.613 h3
  text "mils" at 124.58,-16.517 h2.54
  text "mils" at 135.634,-16.517 h2.54
  text ".Layer_Name" at 9.421,-20.18 h3
  text ".DRL" at 51.116,-20.18 h3
Mechanical 20:
  circle w0.254: c87.425,-26.9 r1.3
  region: 72.947,-27.994 62.191,-27.994 63.184,-25.501 71.042,-25.501 71.491,-24.741 73.699,-27.29
  region: 86.95,-19.664 71.423,-19.664 70.729,-21.439 69.518,-22.664 68.121,-20.804 68.121,-19.153 69.264,-17.756 70.7,-17.378 86.95,-17.378
  lines w0.254: 63.184,-25.501 71.976,-25.501 68.91,-21.963 cw(c70.714,-20.019) 70.954,-17.378 87.718,-17.378 86.956,-19.664 ; 66.498,-17.131 cw(c68.924,-18.101) 69.161,-15.499 ; 66.537,-17.099 62.191,-27.994 81.513,-27.994 ccw(c81.762,-25.259) 84.311,-26.279 ; 68.277,-21.033 73.699,-27.29 ; 68.531,-21.033 73.836,-27.154 ; 68.531,-20.779 73.836,-26.9 ; 68.629,-19.664 81.622,-19.664 ; 68.658,-20.652 73.963,-26.773 ; 68.785,-20.525 74.09,-26.646 ; 68.912,-20.398 74.217,-26.519 ; 69.039,-20.271 74.344,-26.392 ; 69.094,-18.319 74.399,-24.44 ; 69.162,-15.499 88.612,-15.499 84.312,-26.277 ; 69.166,-20.144 74.416,-26.203 ; 69.166,-19.89 74.471,-26.011 ; 69.166,-19.636 74.471,-25.757 ; 69.166,-18.747 74.471,-24.868 ; 69.293,-19.509 74.598,-25.63 ; 69.293,-19.128 74.598,-25.249 ; 70.665,-25.514 ccw(c70.77,-24.979) 71.067,-24.522 ; 71.751,-19.651 ccw(c71.725,-20.218) 71.395,-20.68 73.76,-23.409 cw(c71.956,-25.353) 72.689,-27.901 ; 78.032,-27.789 80.922,-19.41 ; 78.255,-27.74 81.124,-19.419 ; 78.382,-27.74 81.251,-19.419 ; 78.636,-27.74 81.505,-19.419 ; 78.89,-27.74 81.759,-19.419 ; 79.144,-27.74 82.013,-19.419 ; 79.398,-27.74 82.267,-19.419 ; 79.652,-27.74 82.521,-19.419 ; 79.906,-27.74 82.775,-19.419 ; 80.16,-27.74 83.029,-19.419 ; 80.368,-27.789 83.258,-19.41 ; 83.258,-19.664 86.95,-19.664 ; 86.282,-19.661 87.044,-17.375 ; 86.448,-19.664 87.21,-17.378 ; 86.702,-19.664 87.464,-17.378
  lines w0.3: 0.421,-26.88 60.421,-26.88 ; 0.421,-21.88 60.421,-21.88 ; 0.421,-16.88 60.421,-16.88 ; 40.421,-31.88 40.421,-16.88 ; 60.421,-31.88 60.421,-11.88 ; 78.032,-27.789 80.368,-27.789 ; 0.421,-31.88 90.421,-31.88 90.421,-11.88 0.421,-11.88 0.421,-31.88
  text "Project: '.Board_Name'" at 1.421,-15.096 h3
  text "Layer:" at 1.421,-20.18 h3
  text "Gerber:" at 41.41,-20.18 h3
  text "Variant: '.VariantName'" at 1.421,-25.18 h3
  text "Ref: '.Board_Reference'" at 41.537,-25.18 h3
  text "R" at 86.917,-27.662 h1.52
  text "Date: '.Board_Document_Date'" at 1.421,-30.18 h3
  text "Rev: '.Board_PCB_Revision'" at 41.48,-30.18 h3
Mechanical 21:
  circle w0.254: c3.434,-21.9 r1.3
  region: 3.909,-14.664 19.436,-14.664 20.131,-16.439 21.341,-17.664 22.738,-15.804 22.738,-14.153 21.595,-12.756 20.159,-12.378 3.909,-12.378
  region: 17.912,-22.994 28.668,-22.994 27.675,-20.501 19.817,-20.501 19.369,-19.741 17.16,-22.29
  lines w0.254: 3.395,-12.378 4.157,-14.664 ; 3.649,-12.378 4.411,-14.664 ; 3.815,-12.375 4.577,-14.661 ; 3.903,-14.664 3.141,-12.378 19.905,-12.378 cw(c20.146,-15.019) 21.949,-16.963 18.883,-20.501 27.675,-20.501 ; 3.909,-14.664 7.602,-14.664 ; 6.547,-21.277 2.248,-10.499 21.697,-10.499 ; 6.548,-21.279 ccw(c9.097,-20.259) 9.346,-22.994 28.668,-22.994 24.322,-12.099 ; 7.602,-14.41 10.491,-22.789 ; 7.83,-14.419 10.7,-22.74 ; 8.084,-14.419 10.954,-22.74 ; 8.338,-14.419 11.208,-22.74 ; 8.592,-14.419 11.462,-22.74 ; 8.846,-14.419 11.716,-22.74 ; 9.1,-14.419 11.97,-22.74 ; 9.237,-14.664 22.23,-14.664 ; 9.354,-14.419 12.224,-22.74 ; 9.608,-14.419 12.478,-22.74 ; 9.735,-14.419 12.605,-22.74 ; 9.938,-14.41 12.827,-22.789 ; 16.261,-20.63 21.566,-14.509 ; 16.261,-20.249 21.566,-14.128 ; 16.388,-21.011 21.693,-14.89 ; 16.388,-20.757 21.693,-14.636 ; 16.388,-19.868 21.693,-13.747 ; 16.443,-21.203 21.693,-15.144 ; 16.461,-19.44 21.766,-13.319 ; 16.515,-21.392 21.82,-15.271 ; 16.642,-21.519 21.947,-15.398 ; 16.769,-21.646 22.074,-15.525 ; 16.896,-21.773 22.201,-15.652 ; 17.023,-22.154 22.328,-16.033 ; 17.023,-21.9 22.328,-15.779 ; 17.16,-22.29 22.582,-16.033 ; 18.171,-22.901 cw(c18.903,-20.353) 17.1,-18.409 19.464,-15.68 ccw(c19.134,-15.218) 19.108,-14.651 ; 19.792,-19.522 ccw(c20.09,-19.979) 20.195,-20.514 ; 21.699,-10.499 cw(c21.935,-13.101) 24.361,-12.131
  lines w0.3: 10.491,-22.789 12.827,-22.789 ; 30.252,-26.88 30.252,-6.88 ; 30.252,-21.88 90.252,-21.88 ; 30.252,-16.88 90.252,-16.88 ; 30.252,-11.88 90.252,-11.88 ; 50.252,-26.88 50.252,-11.88 ; 0.252,-26.88 0.252,-6.88 90.252,-6.88 90.252,-26.88 0.252,-26.88
  text "Project: '.Board_Name'" at 89.058,-10.096 h3
  text "Gerber:" at 49.069,-15.18 h3
  text "Layer:" at 89.057,-15.18 h3
  text "Ref: '.Board_Reference'" at 49.069,-20.18 h3
  text "Variant: '.VariantName'" at 89.058,-20.18 h3
  text "R" at 3.942,-22.662 h1.52
  text "Rev: '.Board_PCB_Revision'" at 49.126,-25.18 h3
  text "Date: '.Board_Document_Date'" at 89.058,-25.18 h3

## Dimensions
0,34.4 to 59.8,34.4 on Dimensions
59.8,0 to 59.8,34.4 on Dimensions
